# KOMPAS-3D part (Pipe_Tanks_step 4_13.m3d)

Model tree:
1. X Axis
2. Y Axis
3. Z Axis  (labels: Valve Dy 150; Pipe Dn 150; Bend 90 Dn 150)
     Òîëùèíà ñòåíêè 1 = 1

Referenced files in C:\Documents and Settings\kashirsky\Мои документы\Camtasia Studio\Pipelines3D\Tanks\: Tanks_step 4.a3d
Referenced files in C:\Program Files\ASCON\KOMPAS-3D V10\Libs\Piping\LOAD\: Piping_C_Pipe_150_1000.m3d
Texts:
  Pipe Dn 150
  Steel ASTM A295
  Three Point Plane
  Plane at Angle
  Line and Point Plane
  Axis through Two Vertices
  Axis of Feature
  Axis of Conical Surface
  Axis through Edge
  Trim by Surface
  Trim by Sketch
  Feature with No History
  Intersection Axis of Two Planes
  Two Line Plane
  Line and Face Plane
  Bend by line
  Hole in sheet body
  Cut in sheet body
  Point in CM
  Linear Dimension from Line to Point
  Surface Finish Symbol
  Geometric Tolerance Symbol
  Leader #1
  Leader #2
  Leader #3
  Shape Deviations and Datum
  Node point number
  Mark of coordination axis
  Node point designation
  Mark/Reference designation with leader
  Mark/reference designation on line
  Mark/Reference designation without leader
  Valve Dy 150
  Bend 90 Dn 150
  Plane of section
